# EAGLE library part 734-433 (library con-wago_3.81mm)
Serie 734, Doppelstock-Stiftleisten Einlötstift abgewinkelt 1 x 1 mm / Series 734, Double-deck male headers Angled solder pin 1 x 1 mm Polzahl / Pole No.: 3 Rastermaß / Pitch: 3.81 mm Bemessungsspannung / Rated Voltage: 160 V Nennstrom / Nominal Current: 10 A Lötstiftlänge: / Solder Pin Length: 3.6 mm Farbe / Color: orange / orange Stand: 01.01.2012. Die jeweils aktuellen Daten zu diesem Artikel finden Sie in unserem Produktkatalog, den Sie unter www.wago.com einsehen können. As of: 01/01/2012. Please find the newest data for this article in our product catalogue, which can be viewed under www.wago.com.
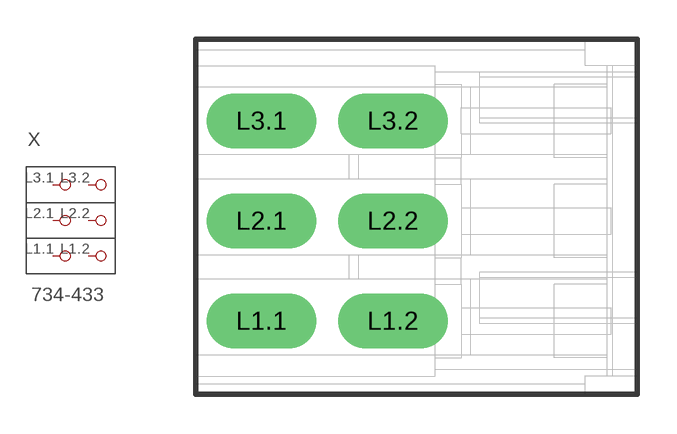
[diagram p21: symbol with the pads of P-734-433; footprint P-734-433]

Designator prefix X

## 734-433  [P-734-433]
L1.1  P1.1
L1.2  P1.2
L2.1  P2.1
L2.2  P2.2
L3.1  P3.1
L3.2  P3.2

## Footprint P-734-433 (pad centres in mm)
drill 1.4 long: L1.1 -5.9,-3.96; L1.2 -0.9,-3.96; L2.1 -5.9,-0.15; L2.2 -0.9,-0.15; L3.1 -5.9,3.66; L3.2 -0.9,3.66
